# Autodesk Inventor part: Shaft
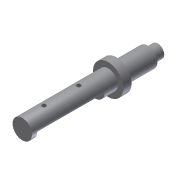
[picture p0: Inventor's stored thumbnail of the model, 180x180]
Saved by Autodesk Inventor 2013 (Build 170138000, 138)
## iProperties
Created: 2009-04
Part Number: Shaft
Document SubType Name: Modeling
Designer: Sham
Density: 1 g/cm^3
Material: Generic
Author: Sham
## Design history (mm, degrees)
sketch "Sketch1"
  geometry: C1 r 18.75 at (511.175, 103.188)
  constraints: 1 centre point
  dimensions: "d0" = 37.5 diameter of C1
extrude "Extrusion1" new body sketch "Sketch1" distance "d1" = 28.9; taper "d2" = 0 deg
sketch "Sketch2"
  geometry: C1 r 28 at (0, 0)
  constraints: 1 centre point
  dimensions: "d3" = 56 diameter of C1
extrude "Extrusion2" join sketch "Sketch2" distance "d4" = 89.8; taper "d5" = 0 deg
sketch "Sketch3"
  geometry: C1 r 43.6 at (0, 0)
  constraints: 1 centre point
  dimensions: "d6" = 87.2 diameter of C1
extrude "Extrusion3" join sketch "Sketch3" distance "d7" = 24; taper "d8" = 0 deg
sketch "Sketch4"
  geometry: C1 r 43.6 at (0, 0) reference; C2 r 28 at (0, 0)
  constraints: 1 centre point, 1 coincident
  dimensions: "d9" = 56 diameter of C2
extrude "Extrusion4" join sketch "Sketch4" distance "d10" = 247.1; taper "d11" = 0 deg
workplane "Work Plane1"
sketch "Sketch5"
  geometry: L1 (28, 0)-(-28, 0); C1 r 43.6 at (0, 0) reference; A1 r 28 centre (0, 0) between (-28, 0) and (28, 0)
  constraints: 2 end point, 2 point on circle, 1 centre point, 1 concentric, 1 horizontal
  dimensions: "d13" = 56 diameter of A1
extrude "Extrusion5" cut sketch "Sketch5" distance "d14" = 193.8; taper "d15" = 0 deg
hole "Hole1" diameter "d18" = 12.5; stored, may be unused: countersink angle "d22" = 90 deg, drill point angle "d24" = 118 deg; dims "d16" = 28, "d17" = 46.9, "d19" = 6, "d20" = 4, "d21" = 2, "d23" = 8
pattern_linear "Rectangular Pattern1" dims "d27" = 100
body "Solid1"
other parameters: "d12" = -15.1
